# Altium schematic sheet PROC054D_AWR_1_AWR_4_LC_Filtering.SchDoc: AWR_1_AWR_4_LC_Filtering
size 558 x 431 mm; Date: Not shown in title block; ApprovedBy: Not shown in title block; CheckedBy: Not shown in title block; Author: Not shown in title block; CompanyName: Not shown in title block; DrawnBy: a0271760; Engineer: Not shown in title block; Organization: Not shown in title block; Address1: Not shown in title block; Address2: Not shown in title block; Address3: Not shown in title block; Address4: Not shown in title block; DocumentNumber: 6; Revision: Use project pAWRameter SCH_Rev; SheetNumber: 6; SheetTotal: 19; PageSetup: Record=PageOptions¦CenterHorizontal=True¦CenterVertical=True¦PrintScale=1.00¦XCorrection=1.00¦YCorrection=1.00¦PrintKind=0¦BorderSize=5000000¦LeftOffset=0¦BottomOffset=0¦Orientation=2¦PaperLength=1000¦PaperWidth=1000¦Scale=100¦PaperSource=15¦PrintQuality=600¦MediaType=1¦DitherType=10¦PaperKind=Letter¦PrintScaleMode=1
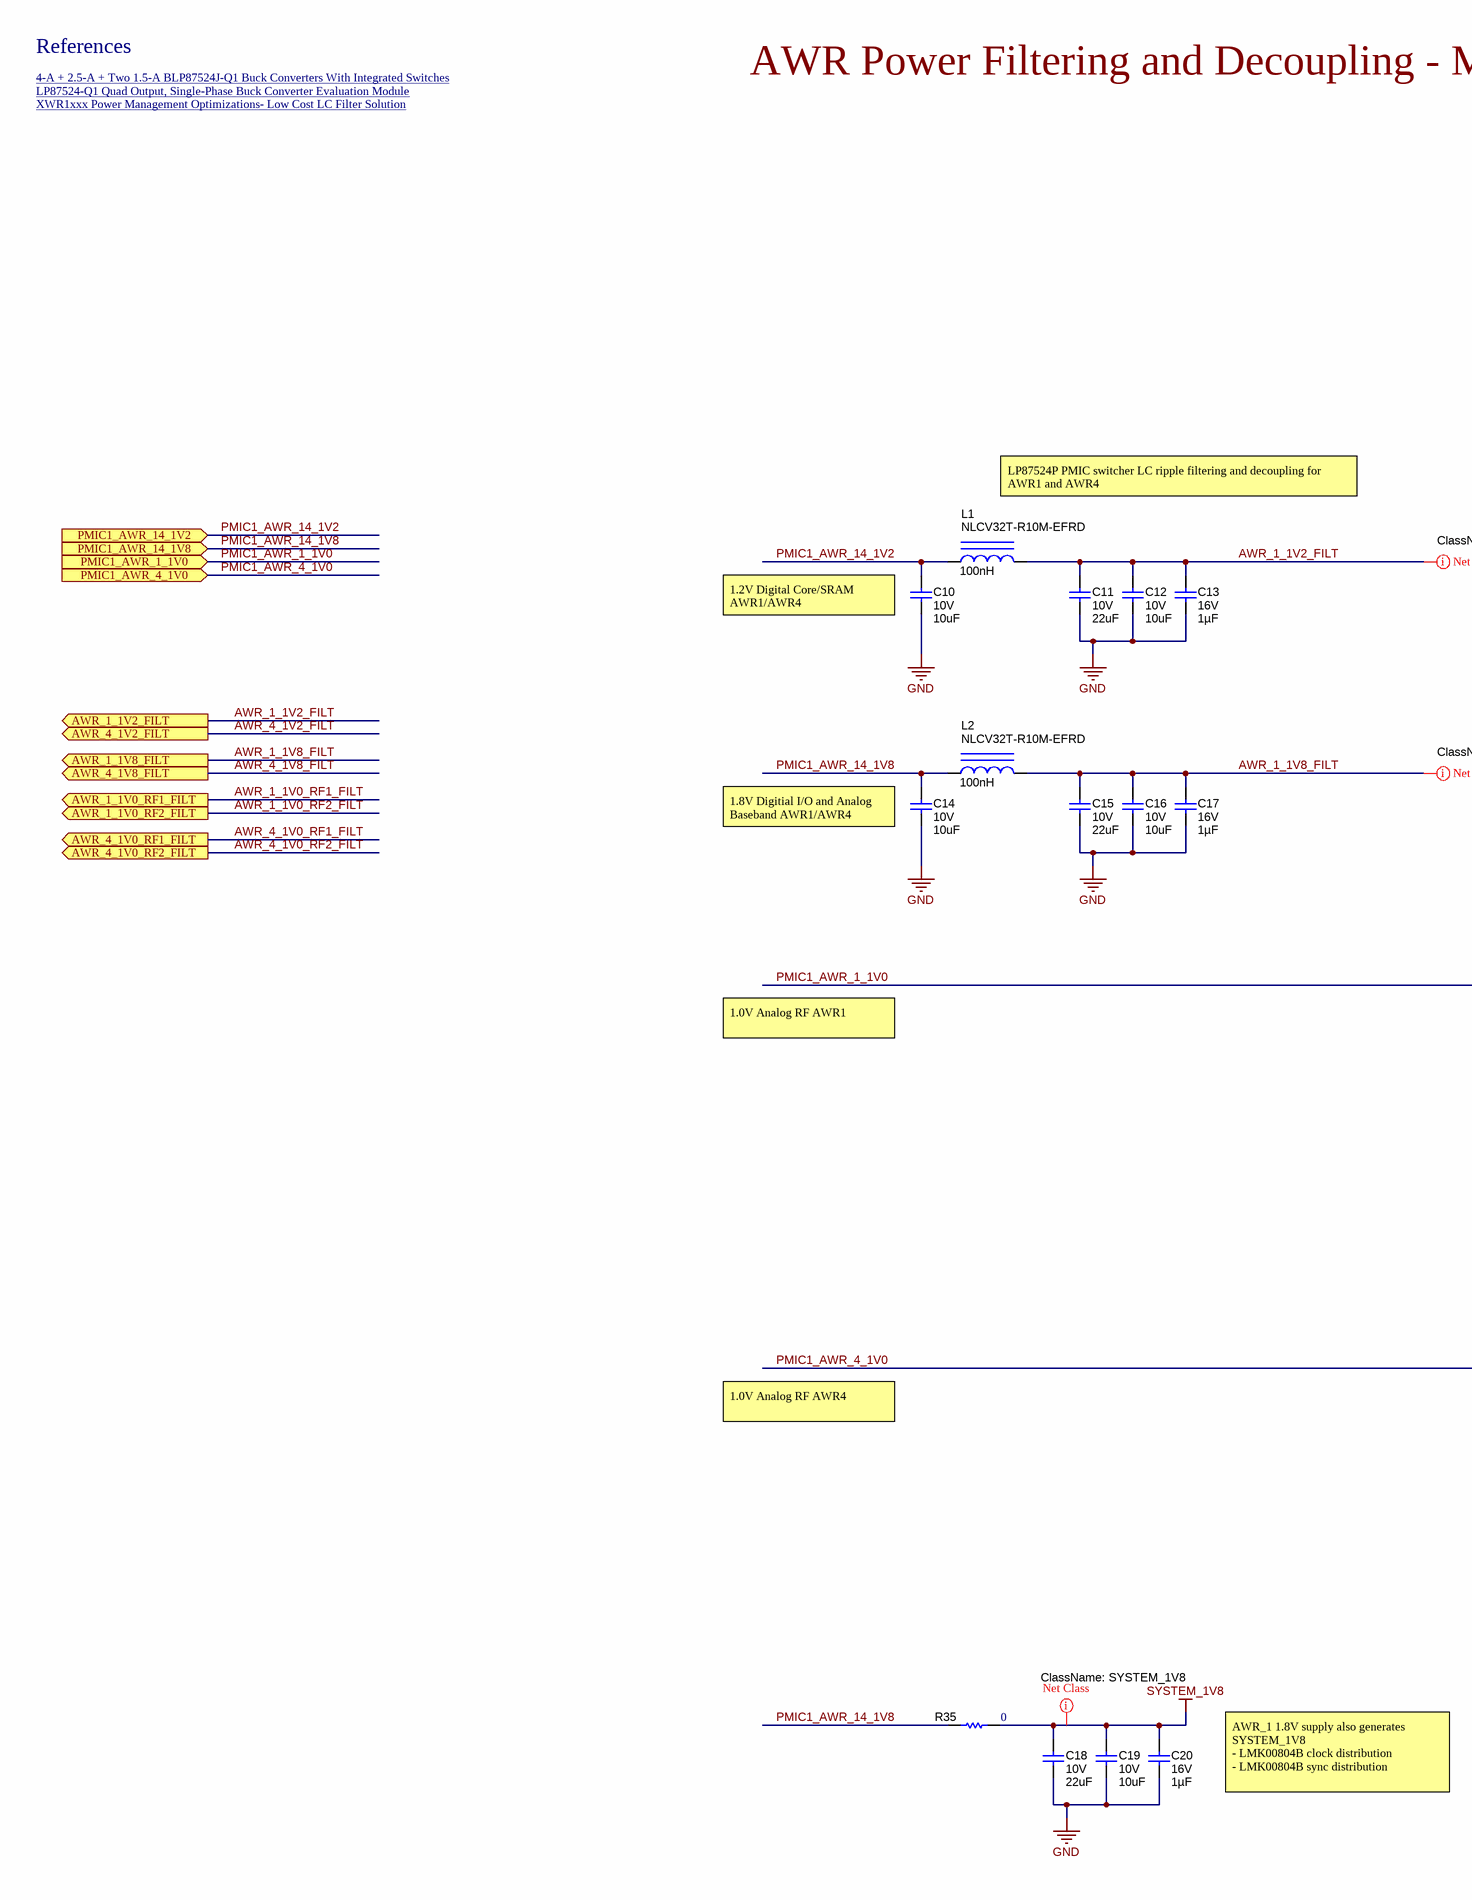
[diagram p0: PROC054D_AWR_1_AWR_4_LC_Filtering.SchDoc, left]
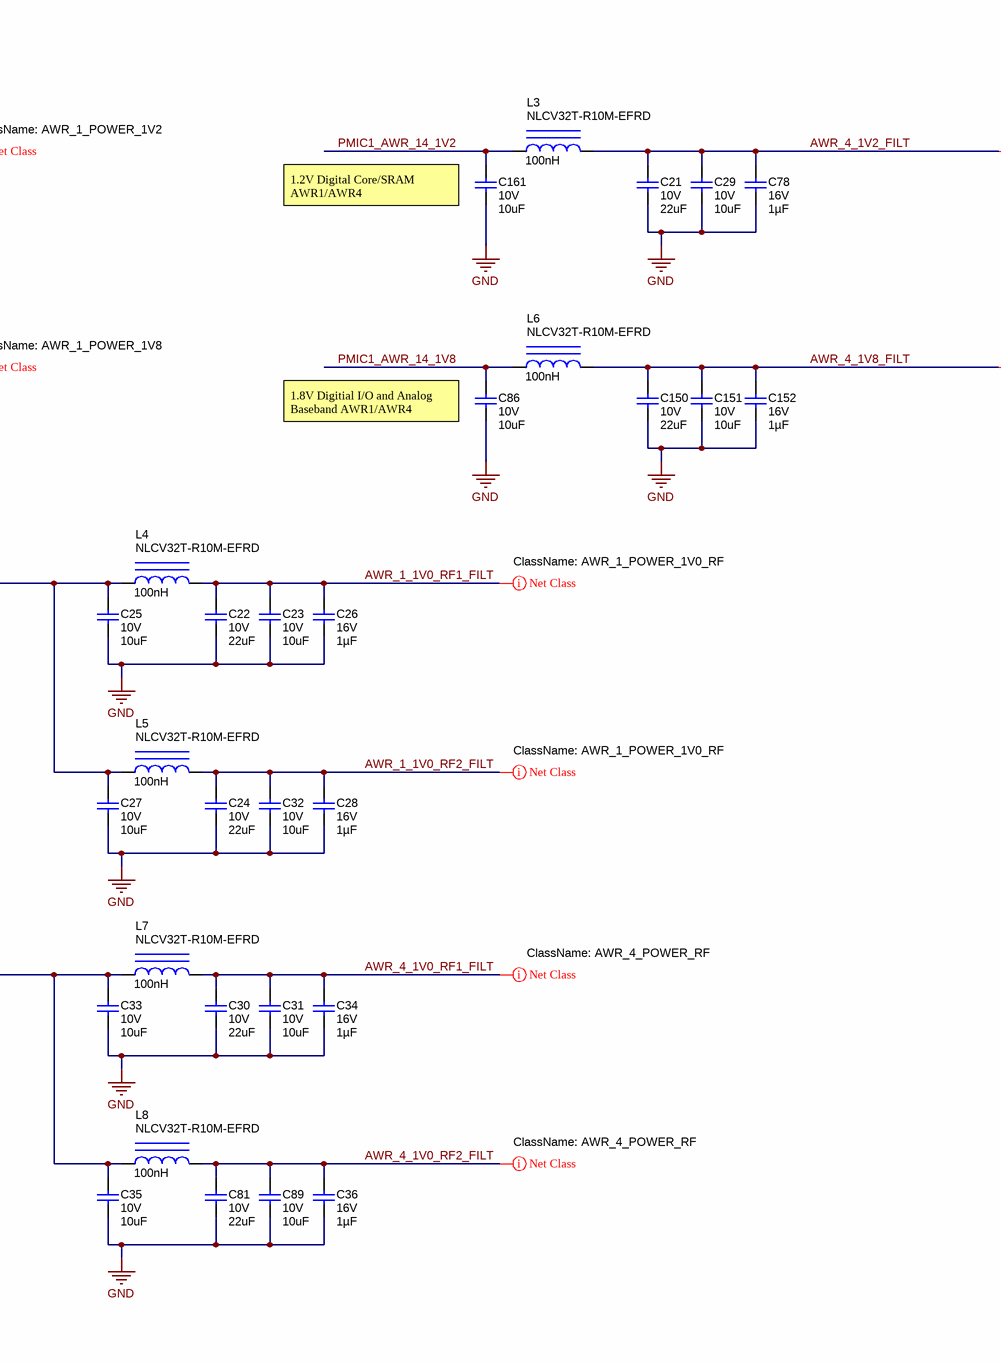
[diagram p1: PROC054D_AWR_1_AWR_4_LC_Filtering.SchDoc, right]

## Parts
C10  VDC_V: 10V  ValueDisplayed: 10uF  [0805L]  (hidden comment: GCM21BR71A106KE22L)
C11  VDC_V: 10V  ValueDisplayed: 22uF  [1206_180L]  (hidden comment: GCM31CR71A226KE02)
C12  VDC_V: 10V  ValueDisplayed: 10uF  [0805L]  (hidden comment: GCM21BR71A106KE22L)
C13  VDC_V: 16V  ValueDisplayed: 1µF  [0603S]  (hidden comment: GCM188R71C105KA64J)
C14  VDC_V: 10V  ValueDisplayed: 10uF  [0805L]  (hidden comment: GCM21BR71A106KE22L)
C15  VDC_V: 10V  ValueDisplayed: 22uF  [1206_180L]  (hidden comment: GCM31CR71A226KE02)
C16  VDC_V: 10V  ValueDisplayed: 10uF  [0805L]  (hidden comment: GCM21BR71A106KE22L)
C17  VDC_V: 16V  ValueDisplayed: 1µF  [0603S]  (hidden comment: GCM188R71C105KA64J)
C18  VDC_V: 10V  ValueDisplayed: 22uF  [1206_180L]  (hidden comment: GCM31CR71A226KE02)
C19  VDC_V: 10V  ValueDisplayed: 10uF  [0805L]  (hidden comment: GCM21BR71A106KE22L)
C20  VDC_V: 16V  ValueDisplayed: 1µF  [0603S]  (hidden comment: GCM188R71C105KA64J)
C21  VDC_V: 10V  ValueDisplayed: 22uF  [1206_180L]  (hidden comment: GCM31CR71A226KE02)
C22  VDC_V: 10V  ValueDisplayed: 22uF  [1206_180L]  (hidden comment: GCM31CR71A226KE02)
C23  VDC_V: 10V  ValueDisplayed: 10uF  [0805L]  (hidden comment: GCM21BR71A106KE22L)
C24  VDC_V: 10V  ValueDisplayed: 22uF  [1206_180L]  (hidden comment: GCM31CR71A226KE02)
C25  VDC_V: 10V  ValueDisplayed: 10uF  [0805L]  (hidden comment: GCM21BR71A106KE22L)
C26  VDC_V: 16V  ValueDisplayed: 1µF  [0603S]  (hidden comment: GCM188R71C105KA64J)
C27  VDC_V: 10V  ValueDisplayed: 10uF  [0805L]  (hidden comment: GCM21BR71A106KE22L)
C28  VDC_V: 16V  ValueDisplayed: 1µF  [0603S]  (hidden comment: GCM188R71C105KA64J)
C29  VDC_V: 10V  ValueDisplayed: 10uF  [0805L]  (hidden comment: GCM21BR71A106KE22L)
C30  VDC_V: 10V  ValueDisplayed: 22uF  [1206_180L]  (hidden comment: GCM31CR71A226KE02)
C31  VDC_V: 10V  ValueDisplayed: 10uF  [0805L]  (hidden comment: GCM21BR71A106KE22L)
C32  VDC_V: 10V  ValueDisplayed: 10uF  [0805L]  (hidden comment: GCM21BR71A106KE22L)
C33  VDC_V: 10V  ValueDisplayed: 10uF  [0805L]  (hidden comment: GCM21BR71A106KE22L)
C34  VDC_V: 16V  ValueDisplayed: 1µF  [0603S]  (hidden comment: GCM188R71C105KA64J)
C35  VDC_V: 10V  ValueDisplayed: 10uF  [0805L]  (hidden comment: GCM21BR71A106KE22L)
C36  VDC_V: 16V  ValueDisplayed: 1µF  [0603S]  (hidden comment: GCM188R71C105KA64J)
C78  VDC_V: 16V  ValueDisplayed: 1µF  [0603S]  (hidden comment: GCM188R71C105KA64J)
C81  VDC_V: 10V  ValueDisplayed: 22uF  [1206_180L]  (hidden comment: GCM31CR71A226KE02)
C86  VDC_V: 10V  ValueDisplayed: 10uF  [0805L]  (hidden comment: GCM21BR71A106KE22L)
C89  VDC_V: 10V  ValueDisplayed: 10uF  [0805L]  (hidden comment: GCM21BR71A106KE22L)
C150  VDC_V: 10V  ValueDisplayed: 22uF  [1206_180L]  (hidden comment: GCM31CR71A226KE02)
C151  VDC_V: 10V  ValueDisplayed: 10uF  [0805L]  (hidden comment: GCM21BR71A106KE22L)
C152  VDC_V: 16V  ValueDisplayed: 1µF  [0603S]  (hidden comment: GCM188R71C105KA64J)
C161  VDC_V: 10V  ValueDisplayed: 10uF  [0805L]  (hidden comment: GCM21BR71A106KE22L)
L1  ValueDisplayed: 100nH  [NLCV32]  (hidden comment: NLCV32T-R10M-EFRD)
L2  ValueDisplayed: 100nH  [NLCV32]  (hidden comment: NLCV32T-R10M-EFRD)
L3  ValueDisplayed: 100nH  [NLCV32]  (hidden comment: NLCV32T-R10M-EFRD)
L4  ValueDisplayed: 100nH  [NLCV32]  (hidden comment: NLCV32T-R10M-EFRD)
L5  ValueDisplayed: 100nH  [NLCV32]  (hidden comment: NLCV32T-R10M-EFRD)
L6  ValueDisplayed: 100nH  [NLCV32]  (hidden comment: NLCV32T-R10M-EFRD)
L7  ValueDisplayed: 100nH  [NLCV32]  (hidden comment: NLCV32T-R10M-EFRD)
L8  ValueDisplayed: 100nH  [NLCV32]  (hidden comment: NLCV32T-R10M-EFRD)
R35  ValueDisplayed: 0  [0805_HV]  (hidden comment: PMR10EZPJ000)

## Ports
AWR_1_1V0_RF1_FILT (out), AWR_1_1V0_RF2_FILT (out), AWR_1_1V2_FILT (out), AWR_1_1V8_FILT (out), AWR_4_1V0_RF1_FILT (out), AWR_4_1V0_RF2_FILT (out), AWR_4_1V2_FILT (out), AWR_4_1V8_FILT (out), PMIC1_AWR_1_1V0 (in), PMIC1_AWR_4_1V0 (in), PMIC1_AWR_14_1V2 (in), PMIC1_AWR_14_1V8 (in)

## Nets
GND: C10.2 C11.2 C12.2 C13.2 C14.2 C15.2 C16.2 C17.2 C18.2 C19.2 C20.2 C21.2 C22.2 C23.2 C24.2 C25.2 C26.2 C27.2 C28.2 C29.2 C30.2 C31.2 C32.2 C33.2 C34.2 C35.2 C36.2 C78.2 C81.2 C86.2 C89.2 C150.2 C151.2 C152.2 C161.2
SYSTEM_1V8: C18.1 C19.1 C20.1 R35.2
AWR_1_1V0_RF1_FILT: C22.1 C23.1 C26.1 L4.2 ; port AWR_1_1V0_RF1_FILT
AWR_1_1V0_RF2_FILT: C24.1 C28.1 C32.1 L5.2 ; port AWR_1_1V0_RF2_FILT
AWR_1_1V2_FILT: C11.1 C12.1 C13.1 L1.2 ; port AWR_1_1V2_FILT
AWR_1_1V8_FILT: C15.1 C16.1 C17.1 L2.2 ; port AWR_1_1V8_FILT
AWR_4_1V0_RF1_FILT: C30.1 C31.1 C34.1 L7.2 ; port AWR_4_1V0_RF1_FILT
AWR_4_1V0_RF2_FILT: C36.1 C81.1 C89.1 L8.2 ; port AWR_4_1V0_RF2_FILT
AWR_4_1V2_FILT: C21.1 C29.1 C78.1 L3.2 ; port AWR_4_1V2_FILT
AWR_4_1V8_FILT: C150.1 C151.1 C152.1 L6.2 ; port AWR_4_1V8_FILT
PMIC1_AWR_1_1V0: C25.1 C27.1 L4.1 L5.1 ; port PMIC1_AWR_1_1V0
PMIC1_AWR_4_1V0: C33.1 C35.1 L7.1 L8.1 ; port PMIC1_AWR_4_1V0
PMIC1_AWR_14_1V2: C10.1 C161.1 L1.1 L3.1 ; port PMIC1_AWR_14_1V2
PMIC1_AWR_14_1V8: C14.1 C86.1 L2.1 L6.1 R35.1 ; port PMIC1_AWR_14_1V8

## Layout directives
net class AWR_1_POWER_1V2: AWR_1_1V2_FILT
net class AWR_1_POWER_1V0_RF: AWR_1_1V0_RF1_FILT, AWR_1_1V0_RF2_FILT
net class AWR_4_POWER_RF: AWR_4_1V0_RF1_FILT, AWR_4_1V0_RF2_FILT
net class SYSTEM_1V8: SYSTEM_1V8
net class AWR_1_POWER_1V8: AWR_1_1V8_FILT
net class AWR_4_POWER_1V2: AWR_4_1V2_FILT
net class AWR_4_POWER_1V8: AWR_4_1V8_FILT

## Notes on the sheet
- References
- LP87524-Q1 Quad Output, Single-Phase Buck Converter Evaluation Module <http://www.ti.com/tool/lp87524q1evm>
- XWR1xxx Power Management Optimizations- Low Cost LC Filter Solution <http://www.ti.com/lit/pdf/swra577>
- 4-A + 2.5-A + Two 1.5-A BLP87524J-Q1 Buck Converters With Integrated Switches <http://www.ti.com/product/lp87524j-q1>
- AWR Power Filtering and Decoupling - Master AWR_1 and Slave AWR_4
- LP87524P PMIC switcher LC ripple filtering and decoupling for AWR1 and AWR4
- (near C10) 1.2V Digital Core/SRAM AWR1/AWR4
- (near C161) 1.2V Digital Core/SRAM AWR1/AWR4
- (near C14) 1.8V Digitial I/O and Analog Baseband AWR1/AWR4
- (near C86) 1.8V Digitial I/O and Analog Baseband AWR1/AWR4
- 1.0V Analog RF AWR1
- 1.0V Analog RF AWR4
- AWR_1 1.8V supply also generates SYSTEM_1V8
  - LMK00804B clock distribution
  - LMK00804B sync distribution

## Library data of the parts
C10 C12 C14 C16 C23 C25 C27 C29 C31-C33 C35 C86 C89 C151 C161 = CMP-0008017-2: CAP, CERM, 10 uF, 10 V, +/- 10%, X7R, 0805; Manufacturer: MuRata; TaMin_C: -55°C; Polarized: N; SizeAreaWB_mm2: 6.75; Value1: Unknown; U/M: EA; Value: 10uF; TaMax_C: 125°C; SizeZ_mm: 1.45; SizeX_mm: 2; SizeY_mm: 1.25; Cap_Case: 0805; SizeArea_mm2: 2.5; Cap_F: 10µF; AEC Category: Q200
C11 C18 = CMP-0008811-2: CAP, CERM, 22 uF, 10 V, +/- 10%, X7R, AEC-Q200 Grade 1, 1206; Manufacturer: MuRata; TaMin_C: -55°C; Polarized: N; SizeAreaWB_mm2: 10.92; Value1: Unknown; U/M: EA; Value: 22uF; TaMax_C: 125°C; SizeZ_mm: 1.8; SizeX_mm: 3.2; SizeY_mm: 1.6; Cap_Case: 1206; SizeArea_mm2: 5.12; CompType: Capacitor; AEC Qualified: Y; Cap_F: 22µF; AEC Grade: 1; AEC Category: Q200
C13 C17 C26 C28 C34 C36 C78 C152 = CMP-0079154-1: CAP, CERM, 1 µF, 16 V,+/- 10%, X7R, AEC-Q200 Grade 1, 0603; Manufacturer: MuRata; SizeAreaWB_mm2: 4.68; SizeArea_mm2: 1.28; AEC Qualified: Y; AEC Category: Q200; Value: 1uF; TaMax_C: 125°C; SizeZ_mm: 1; Polarized: N; TaMin_C: -55°C; SizeY_mm: 0.8; U/M: EA; SizeX_mm: 1.6; Cap_Case: 0603
C15 C21 C22 C24 C30 C81 C150 = CMP-0008811-2: CAP, CERM, 22 uF, 10 V, +/- 10%, X7R, AEC-Q200 Grade 1, 1206; Manufacturer: MuRata; TaMin_C: -55°C; Polarized: N; SizeAreaWB_mm2: 10.92; Value1: Unknown; U/M: EA; Value: 22uF; TaMax_C: 125°C; SizeZ_mm: 1.8; SizeX_mm: 3.2; SizeY_mm: 1.6; Cap_Case: 1206; SizeArea_mm2: 5.12; AEC Qualified: Y; Cap_F: 22µF; AEC Grade: 1; AEC Category: Q200
C19 = CMP-0008017-2: CAP, CERM, 10 uF, 10 V, +/- 10%, X7R, 0805; Manufacturer: MuRata; TaMin_C: -55°C; Polarized: N; SizeAreaWB_mm2: 6.75; Value1: Unknown; U/M: EA; Value: 10uF; TaMax_C: 125°C; SizeZ_mm: 1.45; SizeX_mm: 2; SizeY_mm: 1.25; Cap_Case: 0805; SizeArea_mm2: 2.5; CompType: Capacitor; Cap_F: 10µF; AEC Category: Q200
C20 = CMP-0079154-1: CAP, CERM, 1 µF, 16 V,+/- 10%, X7R, AEC-Q200 Grade 1, 0603; Manufacturer: MuRata; SizeAreaWB_mm2: 4.68; SizeArea_mm2: 1.28; AEC Qualified: Y; AEC Category: Q200; Value: 1uF; TaMax_C: 125°C; SizeZ_mm: 1; Polarized: N; TaMin_C: -55°C; SizeY_mm: 0.8; U/M: EA; CompType: Capacitor; SizeX_mm: 1.6; Cap_Case: 0603
L1-L8 = CMP-0083745-1: Inductor, Wirewound, Ferrite, 100 nH, 2.85 A, 0.024 ohm, AEC-Q200 Grade 1, SMD; Manufacturer: TDK; Isat: 2.85A @ 10% inductance drop; Irms: 2.85A @ 40C rise; SizeAreaWB_mm2: 13.44; DCR_ohm: 0.024; Value: 100nH; Imax_A: 2.85A; SizeZ_mm: 2.5; SizeX_mm: 3.2; SizeY_mm: 2.2; SizeArea_mm2: 7.04; AEC Qualified: Y; AEC Grade: 1; AEC Category: Q200
R35 = CMP-0081857-1: RES, 0, 0%,  W, AEC-Q200 Grade 0, 0805; Manufacturer: Rohm; SizeAreaWB_mm2: 6.75; SizeArea_mm2: 2.5; AEC Qualified: Y; AEC Category: Q200; Value: 0; SizeZ_mm: 1.45; SizeY_mm: 1.25; SizeX_mm: 2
